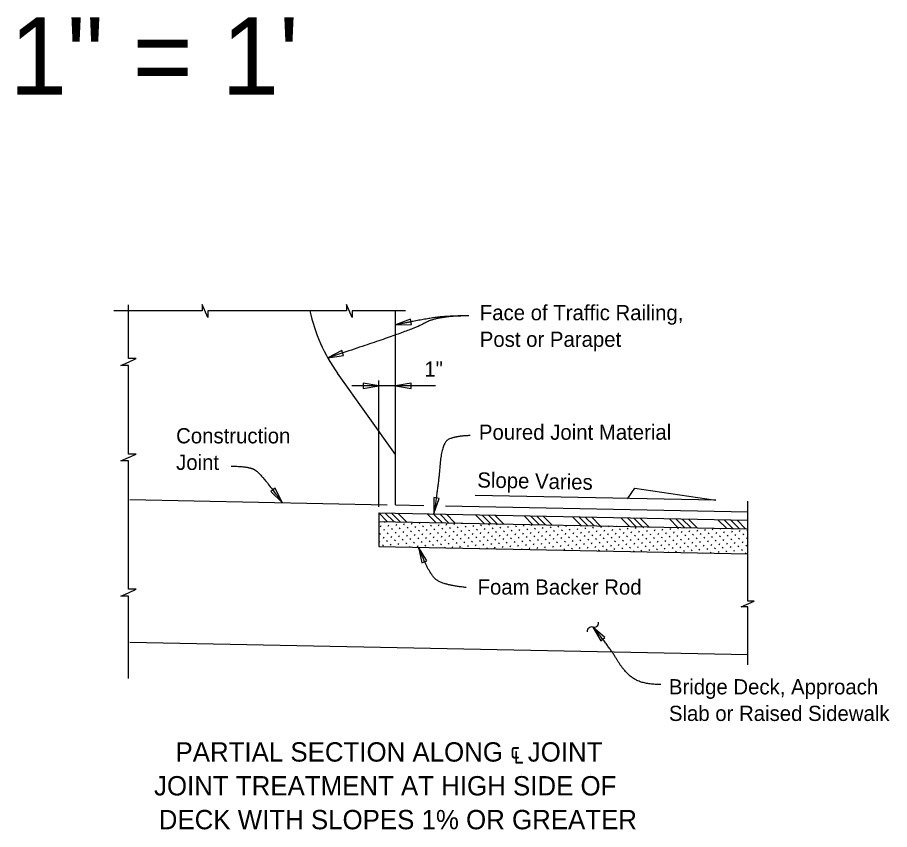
# Model space of a CAD drawing. Extents: x -7.9 to 27, y -3.1 to 14.6.
# Drawn here: x 0.456 to 4.788, y 7.022 to 11.054 of the extents above; entities that cross this region are included whole.
import ezdxf

# ---------------------------------------------------------------- set-up
doc = ezdxf.new("R2010")
doc.units = 0
for name, color, linetype in [('Border', 7, 'Continuous'), ('Patterning', 7, 'Continuous'), ('PlotBorder_dp', 7, 'Continuous'), ('SupstrConc_h', 7, 'Continuous'), ('TextMisc', 7, 'Continuous')]:
    doc.layers.add(name, color=color, linetype=linetype)

msp = doc.modelspace()

# ---------------------------------------------------------------- linework, layer by layer
at = {"layer": 'Patterning'}
for p, q in [((2.3344, 8.8839), (2.3344, 9.5979)), ((2.3344, 8.8839), (2.0461, 9.2875)), ((2.3343, 8.634), (2.3343, 8.884)), ((2.3344, 8.634), (2.4751, 8.6312)), ((2.5831, 8.6291), (4.0844, 8.599)), ((1.0139, 7.9521), (4.0844, 7.8907))]:
    msp.add_line(p, q, dxfattribs=at)
msp.add_arc((2.7242, 9.7718), 0.8333, 192.0469, 215.5377, dxfattribs=at)
at = {"layer": 'PlotBorder_dp'}
for p, q in [((2.251, 8.6235), (2.251, 9.2513)), ((2.5327, 9.2256), (2.1167, 9.2256))]:
    msp.add_line(p, q, dxfattribs=at)
for points in [[(1.5951, 9.5979), (1.4025, 9.5979), (1.4025, 9.5648), (1.3741, 9.6288), (1.3741, 9.5979), (0.9347, 9.5979)], [(1.0081, 8.9169), (1.0081, 9.3265), (0.9693, 9.3265), (1.0081, 9.3433), (1.0468, 9.3602), (1.0081, 9.3602), (1.0081, 9.6276)], [(2.3841, 9.5979), (2.1197, 9.5979), (2.1197, 9.5648), (2.0914, 9.6288), (2.0914, 9.5979), (1.5951, 9.5979)], [(1.0081, 8.5758), (1.0081, 8.8527), (0.9693, 8.8527), (1.0081, 8.8696), (1.0468, 8.8865), (1.0081, 8.8865), (1.0081, 9.1961)], [(3.4859, 8.6648), (3.5224, 8.7172), (3.9259, 8.6573), (2.7293, 8.6812)], [(4.0844, 7.8402), (4.0844, 8.1284), (4.0513, 8.1284), (4.1153, 8.1567), (4.0844, 8.1567), (4.0844, 8.6517)], [(1.0081, 7.7715), (1.0081, 8.1811), (0.9693, 8.1811), (1.0081, 8.1979), (1.0468, 8.2148), (1.0081, 8.2148), (1.0081, 8.5758)]]:
    msp.add_lwpolyline(points, dxfattribs=at)
for points in [[(2.3342, 9.5271), (2.4134, 9.5302), (2.408, 9.5561)], [(1.9981, 9.3646), (2.0765, 9.376), (2.0683, 9.4012)], [(2.2509, 9.2257), (2.1728, 9.2389), (2.1728, 9.2124)], [(2.3343, 9.2257), (2.4124, 9.2124), (2.4124, 9.2389)], [(1.771, 8.6453), (1.7361, 8.7163), (1.7146, 8.7009)], [(2.5246, 8.5915), (2.5505, 8.6663), (2.5244, 8.6707)], [(2.4485, 8.4233), (2.465, 8.3458), (2.4896, 8.3555)], [(3.3146, 8.0273), (3.3544, 7.9588), (3.3748, 7.9757)]]:
    msp.add_lwpolyline(points, close=True, dxfattribs=at)
for centre, start, end in [((3.3084, 8.0056), 74.5069, 186.2341), ((3.3203, 8.0487), 254.5069, 6.2341)]:
    msp.add_arc(centre, 0.0224, start, end, dxfattribs=at)
for points in [[(2.6988, 9.5724), (2.5401, 9.5724), (2.4192, 9.5006), (1.9981, 9.3646)], [(2.6988, 9.5724), (2.5817, 9.5724), (2.4513, 9.5516), (2.3343, 9.5271)], [(2.7043, 8.9781), (2.633, 8.9756), (2.564, 8.9436), (2.5468, 8.7245), (2.5247, 8.5915)], [(1.5187, 8.826), (1.6082, 8.826), (1.669, 8.7866), (1.771, 8.6452)], [(2.6849, 8.2239), (2.5593, 8.2362), (2.4953, 8.3051), (2.4486, 8.4233)], [(3.6527, 7.742), (3.5564, 7.742), (3.4676, 7.8081), (3.3996, 7.9252), (3.3146, 8.0273)]]:
    msp.add_open_spline(points, degree=2, dxfattribs=at)
at = {"layer": 'SupstrConc_h'}
msp.add_line((1.0141, 8.6604), (2.2927, 8.6348), dxfattribs=at)
at = {"layer": 'TextMisc'}
for p, q in [((2.251, 8.594), (2.251, 8.4273)), ((2.251, 8.594), (4.0844, 8.5573)), ((2.251, 8.594), (2.2935, 8.5514)), ((2.2828, 8.5934), (2.3254, 8.5508)), ((2.3147, 8.5927), (2.3572, 8.5502)), ((2.3465, 8.5921), (2.3891, 8.5495)), ((2.4916, 8.5892), (2.5341, 8.5466)), ((2.5234, 8.5885), (2.566, 8.546)), ((2.5553, 8.5879), (2.5978, 8.5453)), ((2.5871, 8.5873), (2.6297, 8.5447)), ((2.7322, 8.5844), (2.7747, 8.5418)), ((2.764, 8.5837), (2.8066, 8.5412)), ((2.7958, 8.5831), (2.8384, 8.5405)), ((2.8277, 8.5825), (2.8702, 8.5399)), ((2.9728, 8.5795), (3.0153, 8.537)), ((3.0046, 8.5789), (3.0472, 8.5364)), ((3.0364, 8.5783), (3.079, 8.5357)), ((3.0683, 8.5776), (3.1108, 8.5351)), ((2.251, 8.5523), (4.0844, 8.5156)), ((2.2804, 8.5467), (2.2833, 8.5516)), ((2.2981, 8.529), (2.3014, 8.5346)), ((2.3191, 8.5499), (2.3197, 8.5509)), ((2.3368, 8.5322), (2.3401, 8.5378)), ((2.3755, 8.5355), (2.3787, 8.5411)), ((2.4142, 8.5387), (2.4174, 8.5443)), ((2.4528, 8.542), (2.4561, 8.5476)), ((2.4915, 8.5452), (2.4928, 8.5474)), ((2.5479, 8.5307), (2.5511, 8.5363)), ((2.5865, 8.534), (2.5898, 8.5396)), ((2.6252, 8.5372), (2.6285, 8.5428)), ((2.6639, 8.5404), (2.6659, 8.544)), ((2.7589, 8.5292), (2.7622, 8.5348)), ((2.7976, 8.5325), (2.8009, 8.538)), ((2.8363, 8.5357), (2.8391, 8.5405)), ((2.875, 8.5389), (2.8754, 8.5398)), ((3.0087, 8.5309), (3.0119, 8.5365)), ((3.0473, 8.5342), (3.0486, 8.5363)), ((3.2134, 8.5747), (3.2559, 8.5322)), ((3.2452, 8.5741), (3.2878, 8.5315)), ((3.277, 8.5735), (3.3196, 8.5309)), ((3.3089, 8.5728), (3.3514, 8.5303)), ((3.4539, 8.5699), (3.4965, 8.5274)), ((3.4858, 8.5693), (3.5283, 8.5267)), ((3.5176, 8.5686), (3.5602, 8.5261)), ((3.5495, 8.568), (3.592, 8.5254)), ((3.6945, 8.5651), (3.7371, 8.5225)), ((3.7264, 8.5645), (3.7689, 8.5219)), ((3.7582, 8.5638), (3.8008, 8.5213)), ((3.79, 8.5632), (3.8326, 8.5206)), ((3.9351, 8.5603), (3.9777, 8.5177)), ((3.967, 8.5596), (4.0095, 8.5171)), ((3.9988, 8.559), (4.0414, 8.5165)), ((4.0306, 8.5584), (4.0732, 8.5158)), ((2.2562, 8.4871), (2.2595, 8.4927)), ((2.2595, 8.5257), (2.2627, 8.5313)), ((2.2772, 8.508), (2.2804, 8.5136)), ((2.2949, 8.4903), (2.2981, 8.4959)), ((2.3159, 8.5113), (2.3191, 8.5169)), ((2.3336, 8.4936), (2.3368, 8.4992)), ((2.3545, 8.5145), (2.3578, 8.5201)), ((2.3722, 8.4968), (2.3755, 8.5024)), ((2.3932, 8.5178), (2.3964, 8.5234)), ((2.4109, 8.5), (2.4142, 8.5056)), ((2.4319, 8.521), (2.4351, 8.5266)), ((2.4496, 8.5033), (2.4528, 8.5089)), ((2.4673, 8.4856), (2.4705, 8.4912)), ((2.4705, 8.5242), (2.4738, 8.5298)), ((2.4883, 8.5065), (2.4915, 8.5121)), ((2.506, 8.4888), (2.5092, 8.4944)), ((2.5092, 8.5275), (2.5124, 8.5331)), ((2.5269, 8.5098), (2.5302, 8.5154)), ((2.5446, 8.4921), (2.5479, 8.4976)), ((2.5656, 8.513), (2.5688, 8.5186)), ((2.5833, 8.4953), (2.5865, 8.5009)), ((2.6043, 8.5162), (2.6075, 8.5218)), ((2.622, 8.4985), (2.6252, 8.5041)), ((2.6429, 8.5195), (2.6462, 8.5251)), ((2.6606, 8.5018), (2.6639, 8.5074)), ((2.6816, 8.5227), (2.6848, 8.5283)), ((2.6993, 8.505), (2.7026, 8.5106)), ((2.717, 8.4873), (2.7203, 8.4929)), ((2.7203, 8.526), (2.7235, 8.5316)), ((2.738, 8.5083), (2.7412, 8.5139)), ((2.7557, 8.4905), (2.7589, 8.4961)), ((2.7767, 8.5115), (2.7799, 8.5171)), ((2.7944, 8.4938), (2.7976, 8.4994)), ((2.8153, 8.5147), (2.8186, 8.5203)), ((2.833, 8.497), (2.8363, 8.5026)), ((2.854, 8.518), (2.8572, 8.5236)), ((2.8717, 8.5003), (2.875, 8.5059)), ((2.8927, 8.5212), (2.8959, 8.5268)), ((2.9104, 8.5035), (2.9136, 8.5091)), ((2.9281, 8.4858), (2.9313, 8.4914)), ((2.9313, 8.5245), (2.9346, 8.5301)), ((2.9491, 8.5067), (2.9523, 8.5123)), ((2.9668, 8.489), (2.97, 8.4946)), ((2.97, 8.5277), (2.9732, 8.5333)), ((2.9877, 8.51), (2.991, 8.5156)), ((3.0054, 8.4923), (3.0087, 8.4979)), ((3.0264, 8.5132), (3.0296, 8.5188)), ((3.0441, 8.4955), (3.0473, 8.5011)), ((3.0651, 8.5165), (3.0683, 8.5221)), ((3.0828, 8.4988), (3.086, 8.5044)), ((3.1037, 8.5197), (3.107, 8.5253)), ((3.1214, 8.502), (3.1247, 8.5076)), ((3.1424, 8.5229), (3.1456, 8.5285)), ((3.1601, 8.5052), (3.1634, 8.5108)), ((3.1778, 8.4875), (3.1811, 8.4931)), ((3.1811, 8.5262), (3.1843, 8.5318)), ((3.1988, 8.5085), (3.202, 8.5141)), ((3.2165, 8.4908), (3.2197, 8.4964)), ((3.2197, 8.5294), (3.2217, 8.5329)), ((3.2375, 8.5117), (3.2407, 8.5173)), ((3.2552, 8.494), (3.2584, 8.4996)), ((3.2761, 8.515), (3.2794, 8.5206)), ((3.2938, 8.4972), (3.2971, 8.5028)), ((3.3148, 8.5182), (3.318, 8.5238)), ((3.3325, 8.5005), (3.3358, 8.5061)), ((3.3535, 8.5214), (3.3567, 8.527)), ((3.3712, 8.5037), (3.3744, 8.5093)), ((3.3889, 8.486), (3.3921, 8.4916)), ((3.3921, 8.5247), (3.3949, 8.5294)), ((3.4098, 8.507), (3.4131, 8.5126)), ((3.4276, 8.4893), (3.4308, 8.4948)), ((3.4308, 8.5279), (3.4312, 8.5287)), ((3.4485, 8.5102), (3.4518, 8.5158)), ((3.4662, 8.4925), (3.4695, 8.4981)), ((3.4872, 8.5134), (3.4904, 8.519)), ((3.5049, 8.4957), (3.5081, 8.5013)), ((3.5259, 8.5167), (3.5291, 8.5223)), ((3.5436, 8.499), (3.5468, 8.5046)), ((3.5645, 8.5199), (3.5678, 8.5255)), ((3.5822, 8.5022), (3.5855, 8.5078)), ((3.6032, 8.5232), (3.6044, 8.5252)), ((3.6209, 8.5055), (3.6242, 8.5111)), ((3.6386, 8.4877), (3.6419, 8.4933)), ((3.6596, 8.5087), (3.6628, 8.5143)), ((3.6773, 8.491), (3.6805, 8.4966)), ((3.6983, 8.5119), (3.7015, 8.5175)), ((3.716, 8.4942), (3.7192, 8.4998)), ((3.7369, 8.5152), (3.7402, 8.5208)), ((3.7546, 8.4975), (3.7579, 8.5031)), ((3.7756, 8.5184), (3.7775, 8.5217)), ((3.7933, 8.5007), (3.7965, 8.5063)), ((3.832, 8.5039), (3.8352, 8.5095)), ((3.8497, 8.4862), (3.8529, 8.4918)), ((3.8706, 8.5072), (3.8739, 8.5128)), ((3.8884, 8.4895), (3.8916, 8.4951)), ((3.9093, 8.5104), (3.9126, 8.516)), ((3.927, 8.4927), (3.9303, 8.4983)), ((3.948, 8.5137), (3.9506, 8.5183)), ((3.9657, 8.496), (3.9689, 8.5016)), ((3.9867, 8.5169), (3.987, 8.5175)), ((4.0044, 8.4992), (4.0076, 8.5048)), ((4.043, 8.5024), (4.0463, 8.508)), ((4.0817, 8.5057), (4.0844, 8.5104)), ((2.253, 8.4484), (2.2562, 8.454)), ((2.2739, 8.4694), (2.2772, 8.475)), ((2.2917, 8.4516), (2.2949, 8.4572)), ((2.3126, 8.4726), (2.3159, 8.4782)), ((2.3303, 8.4549), (2.3336, 8.4605)), ((2.3513, 8.4758), (2.3545, 8.4814)), ((2.369, 8.4581), (2.3722, 8.4637)), ((2.39, 8.4791), (2.3932, 8.4847)), ((2.4077, 8.4614), (2.4109, 8.467)), ((2.4254, 8.4437), (2.4286, 8.4493)), ((2.4286, 8.4823), (2.4319, 8.4879)), ((2.4463, 8.4646), (2.4496, 8.4702)), ((2.4641, 8.4469), (2.4673, 8.4525)), ((2.485, 8.4679), (2.4883, 8.4735)), ((2.5027, 8.4501), (2.506, 8.4557)), ((2.5237, 8.4711), (2.5269, 8.4767)), ((2.5414, 8.4534), (2.5446, 8.459)), ((2.5624, 8.4743), (2.5656, 8.4799)), ((2.5801, 8.4566), (2.5833, 8.4622)), ((2.601, 8.4776), (2.6043, 8.4832)), ((2.6187, 8.4599), (2.622, 8.4655)), ((2.6365, 8.4421), (2.6397, 8.4477)), ((2.6397, 8.4808), (2.6429, 8.4864)), ((2.6574, 8.4631), (2.6606, 8.4687)), ((2.6751, 8.4454), (2.6784, 8.451)), ((2.6784, 8.4841), (2.6816, 8.4897)), ((2.6961, 8.4663), (2.6993, 8.4719)), ((2.7138, 8.4486), (2.717, 8.4542)), ((2.7347, 8.4696), (2.738, 8.4752)), ((2.7525, 8.4519), (2.7557, 8.4575)), ((2.7734, 8.4728), (2.7767, 8.4784)), ((2.7911, 8.4551), (2.7944, 8.4607)), ((2.8121, 8.4761), (2.8153, 8.4817)), ((2.8298, 8.4584), (2.833, 8.464)), ((2.8508, 8.4793), (2.854, 8.4849)), ((2.8685, 8.4616), (2.8717, 8.4672)), ((2.8862, 8.4439), (2.8894, 8.4495)), ((2.8894, 8.4825), (2.8927, 8.4881)), ((2.9071, 8.4648), (2.9104, 8.4704)), ((2.9249, 8.4471), (2.9281, 8.4527)), ((2.9458, 8.4681), (2.9491, 8.4737)), ((2.9635, 8.4504), (2.9668, 8.456)), ((2.9845, 8.4713), (2.9877, 8.4769)), ((3.0022, 8.4536), (3.0054, 8.4592)), ((3.0232, 8.4746), (3.0264, 8.4802)), ((3.0409, 8.4568), (3.0441, 8.4624)), ((3.0618, 8.4778), (3.0651, 8.4834)), ((3.0795, 8.4601), (3.0828, 8.4657)), ((3.0972, 8.4424), (3.1005, 8.448)), ((3.1005, 8.481), (3.1037, 8.4866)), ((3.1182, 8.4633), (3.1214, 8.4689)), ((3.1359, 8.4456), (3.1392, 8.4512)), ((3.1392, 8.4843), (3.1424, 8.4899)), ((3.1569, 8.4666), (3.1601, 8.4722)), ((3.1746, 8.4489), (3.1778, 8.4544)), ((3.1955, 8.4698), (3.1988, 8.4754)), ((3.2133, 8.4521), (3.2165, 8.4577)), ((3.2342, 8.473), (3.2375, 8.4786)), ((3.2519, 8.4553), (3.2552, 8.4609)), ((3.2729, 8.4763), (3.2761, 8.4819)), ((3.2906, 8.4586), (3.2938, 8.4642)), ((3.3116, 8.4795), (3.3148, 8.4851)), ((3.3293, 8.4618), (3.3325, 8.4674)), ((3.347, 8.4441), (3.3502, 8.4497)), ((3.3502, 8.4828), (3.3535, 8.4884)), ((3.3679, 8.4651), (3.3712, 8.4707)), ((3.3857, 8.4473), (3.3889, 8.4529)), ((3.4066, 8.4683), (3.4098, 8.4739)), ((3.4243, 8.4506), (3.4276, 8.4562)), ((3.4453, 8.4715), (3.4485, 8.4771)), ((3.463, 8.4538), (3.4662, 8.4594)), ((3.4839, 8.4748), (3.4872, 8.4804)), ((3.5017, 8.4571), (3.5049, 8.4627)), ((3.5226, 8.478), (3.5259, 8.4836)), ((3.5403, 8.4603), (3.5436, 8.4659)), ((3.558, 8.4426), (3.5613, 8.4482)), ((3.5613, 8.4813), (3.5645, 8.4869)), ((3.579, 8.4635), (3.5822, 8.4691)), ((3.5967, 8.4458), (3.6, 8.4514)), ((3.6, 8.4845), (3.6032, 8.4901)), ((3.6177, 8.4668), (3.6209, 8.4724)), ((3.6354, 8.4491), (3.6386, 8.4547)), ((3.6563, 8.47), (3.6596, 8.4756)), ((3.6741, 8.4523), (3.6773, 8.4579)), ((3.695, 8.4733), (3.6983, 8.4789)), ((3.7127, 8.4556), (3.716, 8.4612)), ((3.7337, 8.4765), (3.7369, 8.4821)), ((3.7514, 8.4588), (3.7546, 8.4644)), ((3.7724, 8.4797), (3.7756, 8.4853)), ((3.7901, 8.462), (3.7933, 8.4676)), ((3.8078, 8.4443), (3.811, 8.4499)), ((3.811, 8.483), (3.8143, 8.4886)), ((3.8287, 8.4653), (3.832, 8.4709)), ((3.8465, 8.4476), (3.8497, 8.4532)), ((3.8674, 8.4685), (3.8706, 8.4741)), ((3.8851, 8.4508), (3.8884, 8.4564)), ((3.9061, 8.4718), (3.9093, 8.4774)), ((3.9238, 8.454), (3.927, 8.4596)), ((3.9447, 8.475), (3.948, 8.4806)), ((3.9625, 8.4573), (3.9657, 8.4629)), ((3.9834, 8.4782), (3.9867, 8.4838)), ((4.0011, 8.4605), (4.0044, 8.4661)), ((4.0188, 8.4428), (4.0221, 8.4484)), ((4.0221, 8.4815), (4.0253, 8.4871)), ((4.0398, 8.4638), (4.043, 8.4694)), ((4.0575, 8.4461), (4.0608, 8.4516)), ((4.0608, 8.4847), (4.064, 8.4903)), ((4.0785, 8.467), (4.0817, 8.4726)), ((2.251, 8.4273), (4.0844, 8.3906)), ((2.2707, 8.4307), (2.2739, 8.4363)), ((2.3094, 8.4339), (2.3126, 8.4395)), ((2.348, 8.4372), (2.3513, 8.4428)), ((2.3689, 8.4249), (2.369, 8.4251)), ((2.3867, 8.4404), (2.39, 8.446)), ((2.4053, 8.4242), (2.4077, 8.4283)), ((2.4431, 8.4259), (2.4463, 8.4315)), ((2.4818, 8.4292), (2.485, 8.4348)), ((2.5204, 8.4324), (2.5237, 8.438)), ((2.5591, 8.4357), (2.5624, 8.4413)), ((2.5784, 8.4207), (2.5801, 8.4235)), ((2.5978, 8.4389), (2.601, 8.4445)), ((2.6155, 8.4212), (2.6187, 8.4268)), ((2.6542, 8.4244), (2.6574, 8.43)), ((2.6928, 8.4277), (2.6961, 8.4333)), ((2.7315, 8.4309), (2.7347, 8.4365)), ((2.7516, 8.4172), (2.7525, 8.4188)), ((2.7702, 8.4342), (2.7734, 8.4398)), ((2.7879, 8.4165), (2.7911, 8.422)), ((2.8088, 8.4374), (2.8121, 8.443)), ((2.8266, 8.4197), (2.8298, 8.4253)), ((2.8475, 8.4406), (2.8508, 8.4462)), ((2.8652, 8.4229), (2.8685, 8.4285)), ((2.9039, 8.4262), (2.9071, 8.4318)), ((2.9247, 8.4138), (2.9249, 8.414)), ((2.9426, 8.4294), (2.9458, 8.435)), ((2.9611, 8.413), (2.9635, 8.4173)), ((2.9812, 8.4326), (2.9845, 8.4382)), ((2.999, 8.4149), (3.0022, 8.4205)), ((3.0199, 8.4359), (3.0232, 8.4415)), ((3.0376, 8.4182), (3.0409, 8.4238)), ((3.0586, 8.4391), (3.0618, 8.4447)), ((3.0763, 8.4214), (3.0795, 8.427)), ((3.115, 8.4247), (3.1182, 8.4303)), ((3.1342, 8.4096), (3.1359, 8.4125)), ((3.1536, 8.4279), (3.1569, 8.4335)), ((3.1713, 8.4102), (3.1746, 8.4158)), ((3.1923, 8.4311), (3.1955, 8.4367)), ((3.21, 8.4134), (3.2133, 8.419)), ((3.231, 8.4344), (3.2342, 8.44)), ((3.2487, 8.4167), (3.2519, 8.4223)), ((3.2696, 8.4376), (3.2729, 8.4432)), ((3.2874, 8.4199), (3.2906, 8.4255)), ((3.3073, 8.4061), (3.3083, 8.4078)), ((3.3083, 8.4409), (3.3116, 8.4465)), ((3.326, 8.4231), (3.3293, 8.4287)), ((3.3437, 8.4054), (3.347, 8.411)), ((3.3647, 8.4264), (3.3679, 8.432)), ((3.3824, 8.4087), (3.3857, 8.4143)), ((3.4034, 8.4296), (3.4066, 8.4352)), ((3.4211, 8.4119), (3.4243, 8.4175)), ((3.442, 8.4329), (3.4453, 8.4385)), ((3.4598, 8.4152), (3.463, 8.4208)), ((3.4807, 8.4361), (3.4839, 8.4417)), ((3.4984, 8.4184), (3.5017, 8.424)), ((3.5169, 8.4019), (3.5194, 8.4063)), ((3.5194, 8.4393), (3.5226, 8.4449)), ((3.5371, 8.4216), (3.5403, 8.4272)), ((3.5548, 8.4039), (3.558, 8.4095)), ((3.5758, 8.4249), (3.579, 8.4305)), ((3.5935, 8.4072), (3.5967, 8.4128)), ((3.6144, 8.4281), (3.6177, 8.4337)), ((3.6321, 8.4104), (3.6354, 8.416)), ((3.6531, 8.4314), (3.6563, 8.437)), ((3.6708, 8.4136), (3.6741, 8.4192)), ((3.6918, 8.4346), (3.695, 8.4402)), ((3.7095, 8.4169), (3.7127, 8.4225)), ((3.7272, 8.3992), (3.7304, 8.4048)), ((3.7304, 8.4378), (3.7337, 8.4434)), ((3.7482, 8.4201), (3.7514, 8.4257)), ((3.7659, 8.4024), (3.7691, 8.408)), ((3.7691, 8.4411), (3.7724, 8.4467)), ((3.7868, 8.4234), (3.7901, 8.429)), ((3.8045, 8.4057), (3.8078, 8.4112)), ((3.8255, 8.4266), (3.8287, 8.4322)), ((3.8432, 8.4089), (3.8465, 8.4145)), ((3.8642, 8.4298), (3.8674, 8.4354)), ((3.8819, 8.4121), (3.8851, 8.4177)), ((3.9028, 8.4331), (3.9061, 8.4387)), ((3.9205, 8.4154), (3.9238, 8.421)), ((3.9415, 8.4363), (3.9447, 8.4419)), ((3.9592, 8.4186), (3.9625, 8.4242)), ((3.9769, 8.4009), (3.9802, 8.4065)), ((3.9802, 8.4396), (3.9834, 8.4452)), ((3.9979, 8.4219), (4.0011, 8.4275)), ((4.0156, 8.4041), (4.0188, 8.4097)), ((4.0366, 8.4251), (4.0398, 8.4307)), ((4.0543, 8.4074), (4.0575, 8.413)), ((4.0752, 8.4283), (4.0785, 8.4339)), ((3.4805, 8.4027), (3.4807, 8.403)), ((3.69, 8.3985), (3.6918, 8.4015)), ((3.8631, 8.395), (3.8642, 8.3968)), ((3.8996, 8.3944), (3.9028, 8.4)), ((3.9383, 8.3977), (3.9415, 8.4033)), ((4.0363, 8.3915), (4.0366, 8.392)), ((4.0726, 8.3908), (4.0752, 8.3953))]:
    msp.add_line(p, q, dxfattribs=at)

# ---------------------------------------------------------------- texts
at = {"layer": 'Border'}
for s, height, p in [('1" = 1\'', 0.384, (0.4172, 10.67)), ('1"', 0.0756, (2.4773, 9.2704)), ('Poured Joint Material', 0.0756, (2.7486, 8.9571)), ('Foam Backer Rod', 0.0756, (2.7419, 8.1884))]:
    msp.add_text(s, height=height, dxfattribs=at).set_placement(p)
msp.add_text('Slope Varies', height=0.0756, rotation=358.8543, dxfattribs=at).set_placement((2.7401, 8.7203))
at = {"layer": 'PlotBorder_dp'}
for s, height, p in [('Face of Traffic Railing, ', 0.0756, (2.7529, 9.5506)), ('Post or Parapet', 0.0756, (2.7529, 9.4186)), ('Construction ', 0.0756, (1.2445, 8.9394)), ('Joint', 0.0756, (1.2445, 8.8074)), ('Bridge Deck, Approach ', 0.0756, (3.6923, 7.6931)), ('Slab or Raised Sidewalk', 0.0756, (3.6923, 7.5611)), ('PARTIAL SECTION ALONG ℄ JOINT', 0.096, (1.2415, 7.3594)), ('JOINT TREATMENT AT HIGH SIDE OF', 0.096, (1.1349, 7.1914)), ('DECK WITH SLOPES 1% OR GREATER', 0.096, (1.1582, 7.0234))]:
    msp.add_text(s, height=height, dxfattribs=at).set_placement(p)

doc.saveas('drawing.dxf')
